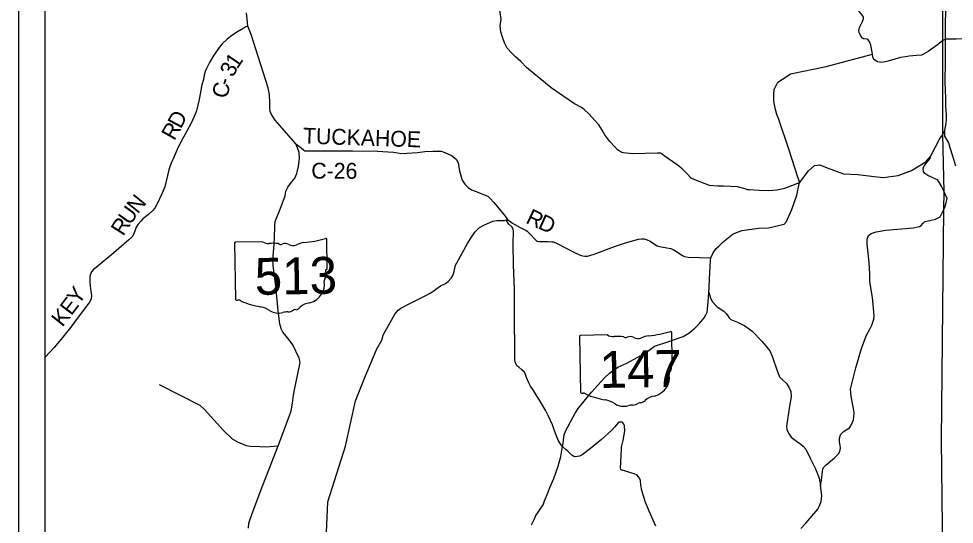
# Model space of a CAD drawing. Extents: x 0 to 2329303, y 0 to 694397.
# Drawn here: x 2 to 5.532, y 18.082 to 19.992 of the extents above; entities that cross this region are included whole.
import ezdxf

# ---------------------------------------------------------------- set-up
doc = ezdxf.new("R2010")
doc.units = 0
for name, color, linetype in [('GM_X_County_Road', 7, 'Continuous'), ('GM_X_County_Road_Text', 7, 'Continuous'), ('GM_X_State_Route', 7, 'Continuous'), ('GM_X_State_Shield', 7, 'Continuous'), ('GM_X_Township', 7, 'Continuous'), ('GM_X_Township_Road', 7, 'Continuous'), ('GM_X_Township_ROW', 7, 'Continuous'), ('SH_Data', 7, 'Continuous')]:
    doc.layers.add(name, color=color, linetype=linetype)

msp = doc.modelspace()

# ---------------------------------------------------------------- linework, layer by layer
at = {"layer": 'GM_X_County_Road'}
for points in [[(2.8652, 19.9647), (2.858, 19.9618), (2.8499, 19.9568), (2.8255, 19.9424), (2.8044, 19.9283), (2.787, 19.9145), (2.7664, 19.8965), (2.7605, 19.889), (2.7373, 19.855), (2.7203, 19.8264), (2.7089, 19.8039), (2.7042, 19.793), (2.7007, 19.7789), (2.6972, 19.7624), (2.6909, 19.7431), (2.6902, 19.7359), (2.6859, 19.715), (2.6813, 19.6877), (2.6712, 19.6443), (2.6626, 19.623), (2.65, 19.5948), (2.6227, 19.5444), (2.6018, 19.5065), (2.5864, 19.4719), (2.5754, 19.4465), (2.5707, 19.4333), (2.5672, 19.4216), (2.5613, 19.3995), (2.5513, 19.3577), (2.5406, 19.3303), (2.5229, 19.2925), (2.5146, 19.2788), (2.5071, 19.2695), (2.49, 19.2529), (2.4689, 19.2363), (2.4605, 19.2274), (2.451, 19.2157), (2.4439, 19.2044), (2.4396, 19.1935), (2.4329, 19.177), (2.4286, 19.1686), (2.4154, 19.1572), (2.3593, 19.1074), (2.2925, 19.0524), (2.2825, 19.0443), (2.2754, 19.0358), (2.271, 19.0273), (2.2687, 19.0177), (2.2681, 18.9968), (2.2707, 18.9712), (2.2732, 18.9543), (2.2748, 18.9467), (2.2738, 18.9331), (2.2674, 18.9218), (2.2555, 18.906), (2.225, 18.8645), (2.1973, 18.8266), (2.1854, 18.8128), (2.1663, 18.7894), (2.1334, 18.7495), (2.1, 18.7133)], [(3.0469, 19.5191), (3.0659, 19.504), (3.0764, 19.4953), (3.0804, 19.4933), (3.0988, 19.4926), (3.2602, 19.4935), (3.3543, 19.4914), (3.3952, 19.4897), (3.4156, 19.4882), (3.4304, 19.4859), (3.4461, 19.4836), (3.4653, 19.4838), (3.5053, 19.4869), (3.5329, 19.4903), (3.5653, 19.4917), (3.5862, 19.4923), (3.595, 19.4916), (3.6094, 19.4873), (3.6335, 19.4754), (3.6456, 19.4667), (3.6533, 19.4599), (3.6594, 19.4463), (3.6648, 19.4174), (3.6702, 19.3954), (3.6747, 19.3822), (3.6844, 19.3674), (3.6965, 19.3551), (3.7102, 19.3463), (3.7271, 19.3396), (3.7608, 19.3259), (3.7713, 19.3215), (3.7805, 19.3136), (3.7943, 19.2984), (3.8331, 19.2517), (3.846, 19.2338), (3.8525, 19.229), (3.8645, 19.2203), (3.8911, 19.2052), (3.9088, 19.1965), (3.9148, 19.1933), (3.92, 19.1902), (3.9305, 19.1786), (3.9495, 19.1579), (3.9568, 19.1523), (3.9668, 19.15), (3.9996, 19.1502), (4.0128, 19.1499), (4.0197, 19.1492), (4.0325, 19.1424), (4.0956, 19.11), (4.1198, 19.0993), (4.1294, 19.0958), (4.1378, 19.0951), (4.1478, 19.0955), (4.173, 19.1033), (4.2492, 19.132), (4.2912, 19.1452), (4.3403, 19.1592), (4.3515, 19.1605), (4.3612, 19.1601), (4.3728, 19.157), (4.3844, 19.1515), (4.3973, 19.1431), (4.4106, 19.1348), (4.4255, 19.1305), (4.4623, 19.1244), (4.4708, 19.1208), (4.4841, 19.1125), (4.4998, 19.101), (4.5066, 19.0974), (4.5134, 19.0934), (4.5279, 19.0919), (4.6135, 19.0889)]]:
    msp.add_lwpolyline(points, dxfattribs=at)
at = {"layer": 'GM_X_State_Route'}
for points in [[(5.4896, 19.5547), (5.4963, 19.5711), (5.5005, 19.5907), (5.503, 19.6107), (5.5027, 19.6294), (5.5009, 19.6616), (5.5008, 19.6926), (5.4982, 19.7527), (5.4993, 19.8307), (5.4998, 19.9151), (5.4988, 19.9776), (5.5001, 20.0174), (5.4999, 20.0298), (5.5007, 20.033)], [(2.8679, 18.0674), (2.8691, 18.0862), (2.871, 18.0943), (2.8812, 18.1226), (2.922, 18.2293), (2.9555, 18.317), (2.9798, 18.379), (2.9978, 18.4249), (3.0229, 18.4936), (3.0285, 18.5106), (3.0336, 18.5396), (3.0378, 18.5702), (3.0428, 18.5963), (3.0608, 18.6806), (3.0619, 18.6874), (3.0625, 18.695), (3.0594, 18.7094), (3.0352, 18.7595), (3.0249, 18.7746), (3.0048, 18.7986), (2.9974, 18.8077), (2.992, 18.8177), (2.9864, 18.8376), (2.9797, 18.8893), (2.9711, 18.9818), (2.9649, 19.0302), (2.9611, 19.0607), (2.9591, 19.0811), (2.9622, 19.1093), (2.9647, 19.1402), (2.9658, 19.1687), (2.9667, 19.2049), (2.9672, 19.2165), (2.9698, 19.2294), (2.985, 19.2666), (3.0056, 19.3232), (3.0092, 19.341), (3.0161, 19.3559), (3.0262, 19.3698), (3.0423, 19.3902), (3.0507, 19.408), (3.0566, 19.4342), (3.0608, 19.466), (3.0592, 19.4868), (3.0532, 19.5044), (3.0469, 19.5191), (2.9953, 19.5783), (2.9682, 19.609), (2.955, 19.6305), (2.9496, 19.6412), (2.9481, 19.654), (2.9482, 19.6729), (2.9467, 19.7061), (2.9414, 19.7309), (2.8953, 19.8771), (2.8776, 19.9321), (2.8652, 19.9647), (2.8627, 19.9922), (2.8606, 20.0144)], [(5.5387, 19.4355), (5.5273, 19.4728), (5.5172, 19.5043), (5.512, 19.5232), (5.4971, 19.5489), (5.4963, 19.5711)], [(3.9361, 18.0806), (3.9472, 18.1029), (3.953, 18.1159), (3.9592, 18.124), (3.9694, 18.139), (3.9798, 18.1557), (3.9855, 18.171), (3.9989, 18.203), (4.005, 18.2212), (4.0207, 18.2552), (4.037, 18.302), (4.0471, 18.3387), (4.0536, 18.3758), (4.0553, 18.3878), (4.0585, 18.4116), (4.0595, 18.42), (4.0648, 18.4338), (4.1004, 18.5015), (4.1128, 18.5194), (4.1628, 18.5813), (4.1867, 18.6075), (4.213, 18.6373), (4.2307, 18.6525), (4.2425, 18.6615), (4.2623, 18.676), (4.2964, 18.6911), (4.3352, 18.7119), (4.363, 18.7273), (4.3799, 18.7405), (4.3906, 18.7479), (4.4005, 18.7545), (4.4542, 18.7728), (4.4939, 18.7869), (4.5094, 18.792), (4.5308, 18.804), (4.5525, 18.8225), (4.5686, 18.8393), (4.5877, 18.8626), (4.5939, 18.8731), (4.5989, 18.8841), (4.6017, 18.907), (4.6046, 18.9392), (4.6058, 18.9586), (4.6067, 18.9737), (4.6088, 19.0111), (4.6107, 19.0549), (4.6114, 19.079), (4.6135, 19.0889), (4.614, 19.0915), (4.6217, 19.1077), (4.633, 19.124), (4.644, 19.1326), (4.6603, 19.1498), (4.6979, 19.1801), (4.7304, 19.1926), (4.7934, 19.2011), (4.8314, 19.2017), (4.8899, 19.2157), (4.898, 19.224), (4.9195, 19.2719), (4.9381, 19.325), (4.9465, 19.3689), (4.9496, 19.3733), (4.9804, 19.4167), (5.0042, 19.4374), (5.0246, 19.44), (5.0525, 19.4287), (5.1143, 19.4067), (5.1689, 19.4034), (5.2303, 19.3962), (5.2636, 19.3919), (5.3211, 19.3994), (5.3705, 19.4188), (5.4225, 19.4503), (5.4436, 19.4746), (5.4766, 19.5376), (5.4896, 19.5547)]]:
    msp.add_lwpolyline(points, dxfattribs=at)
at = {"layer": 'GM_X_State_Shield'}
for p, q in [((2.9206, 19.1493), (2.8187, 19.1476)), ((3.165, 19.0481), (3.1632, 19.1586)), ((2.8153, 19.1439), (2.8189, 18.9326)), ((3.165, 19.0481), (3.165, 19.0481)), ((4.2229, 18.7975), (4.121, 18.7958)), ((4.4674, 18.6963), (4.4655, 18.8069)), ((4.1177, 18.7921), (4.1212, 18.5809)), ((4.4673, 18.6964), (4.4674, 18.6963))]:
    msp.add_line(p, q, dxfattribs=at)
for centre, major_axis, start_param, end_param in [((2.8193, 19.1444), (0.00403, 0.00007), 1.712693, 3.28349), ((2.9444, 19.1742), (0.0391, 0.0007), 4.042523, 4.731795), ((3.0874, 19.0876), (0.0742, 0.0012), 1.699011, 2.107814), ((3.0345, 19.4394), (0.369, 0.0062), 4.814394, 5.042369), ((3.1593, 19.159), (0.00387, 0.00006), 6.141152, 7.989035), ((2.9598, 19.0313), (0.1404, 0.0024), 1.404758, 1.657858), ((2.9897, 19.1484), (0.0113, 0.0002), 3.836095, 5.185415), ((3.0067, 19.1242), (0.0235, 0.0004), 0.950623, 2.079405), ((3.0364, 19.1582), (0.0282, 0.0005), 4.081561, 5.145723), ((3.1643, 19.04), (0.006, 0.0001), 1.883978, 3.671073), ((3.1609, 19.0476), (0.00415, 0.00007), 5.05454, 6.418171), ((3.1797, 19.0021), (0.0262, 0.0004), 2.387724, 3.262537), ((3.1263, 19.0253), (0.036, 0.0006), 5.934695, 6.695948), ((3.0627, 18.986), (0.0923, 0.0015), 5.101752, 6.440018), ((2.8229, 18.9322), (0.00407, 0.00007), 3.00124, 4.508301), ((2.8231, 18.9538), (0.031, 0.0005), 4.665946, 4.897461), ((2.8301, 18.9206), (0.0112, 0.0002), 0.519207, 1.627899), ((2.9682, 19.1128), (0.2665, 0.0045), 4.195997, 4.488961), ((2.8933, 18.8389), (0.0834, 0.0014), 0.823519, 1.323587), ((3.0388, 18.9158), (0.0298, 0.0005), 4.937069, 5.64225), ((3.1035, 18.878), (0.0506, 0.0008), 1.647645, 2.488434), ((2.9821, 18.9221), (0.0529, 0.0009), 4.026481, 4.996735), ((3.0139, 18.8496), (0.0435, 0.0007), 1.495662, 1.94098), ((3.0168, 18.9069), (0.0282, 0.0005), 4.691044, 5.507374), ((3.0426, 18.8868), (0.00794, 0.00013), 1.147584, 2.315152), ((4.1216, 18.7927), (0.00403, 0.00007), 1.712693, 3.28349), ((4.2468, 18.8225), (0.0391, 0.0007), 4.042523, 4.731795), ((4.3898, 18.7358), (0.0742, 0.0012), 1.699011, 2.107814), ((4.3368, 19.0876), (0.369, 0.0062), 4.814394, 5.042369), ((4.4616, 18.8073), (0.00387, 0.00006), 6.141152, 7.989035), ((4.2622, 18.6795), (0.1404, 0.0024), 1.404758, 1.657858), ((4.2921, 18.7966), (0.0113, 0.0002), 3.836095, 5.185415), ((4.3091, 18.7725), (0.0235, 0.0004), 0.950623, 2.079405), ((4.3388, 18.8065), (0.0282, 0.0005), 4.081561, 5.145723), ((4.4666, 18.6882), (0.006, 0.0001), 1.883978, 3.671073), ((4.4632, 18.6958), (0.00415, 0.00007), 5.05454, 6.418171), ((4.482, 18.6503), (0.0262, 0.0004), 2.387724, 3.262537), ((4.4287, 18.6736), (0.036, 0.0006), 5.934695, 6.695948), ((4.3651, 18.6343), (0.0923, 0.0015), 5.101752, 6.440018), ((4.1252, 18.5805), (0.00407, 0.00007), 3.00124, 4.508301), ((4.1255, 18.6021), (0.031, 0.0005), 4.665946, 4.897461), ((4.1324, 18.5688), (0.0112, 0.0002), 0.519207, 1.627899), ((4.2705, 18.7611), (0.2665, 0.0045), 4.195997, 4.488961), ((4.1956, 18.4871), (0.0834, 0.0014), 0.823519, 1.323587), ((4.3411, 18.5641), (0.0298, 0.0005), 4.937069, 5.64225), ((4.4058, 18.5263), (0.0506, 0.0008), 1.647645, 2.488434), ((4.2845, 18.5703), (0.0529, 0.0009), 4.026481, 4.996735), ((4.3163, 18.4978), (0.0435, 0.0007), 1.495662, 1.94098), ((4.3192, 18.5551), (0.0282, 0.0005), 4.691044, 5.507374), ((4.345, 18.5351), (0.00794, 0.00013), 1.147584, 2.315152)]:
    msp.add_ellipse(centre, major_axis=major_axis, ratio=0.8, start_param=start_param, end_param=end_param, dxfattribs=at)
at = {"layer": 'GM_X_Township'}
msp.add_lwpolyline([(5.8223, 14.1123), (5.5, 14.1), (5.5092, 14.6075), (5.4849, 16.2502), (5.4862, 16.3702), (5.4966, 17.3083), (5.484, 18.4012), (5.4927, 19.2711), (5.4941, 19.3381), (5.4896, 19.5547), (5.4893, 19.9096), (5.4898, 20.0261), (5.5032, 20.182), (5.5028, 20.3048), (5.5027, 20.3409), (5.5308, 20.3409), (5.6417, 20.3416)], dxfattribs=at)
at = {"layer": 'GM_X_Township_Road'}
for points in [[(4.9496, 19.3733), (4.9273, 19.365), (4.891, 19.351), (4.864, 19.3449), (4.8309, 19.3422), (4.7961, 19.343), (4.7596, 19.3455), (4.7512, 19.3456), (4.7431, 19.3493), (4.7141, 19.3572), (4.6608, 19.3602), (4.6391, 19.3601), (4.6079, 19.3619), (4.5529, 19.3831), (4.5392, 19.3902), (4.5239, 19.4062), (4.5049, 19.4249), (4.4863, 19.44), (4.4376, 19.4746), (4.4312, 19.4793), (4.4231, 19.4837), (4.4119, 19.4844), (4.3171, 19.4813), (4.2834, 19.4851), (4.2774, 19.487), (4.2609, 19.4973), (4.2504, 19.5077), (4.2322, 19.5288), (4.2136, 19.5532), (4.2034, 19.5708), (4.1905, 19.5911), (4.1771, 19.6071), (4.1521, 19.6326), (4.1344, 19.6489), (4.1243, 19.6564), (4.0982, 19.6703), (4.01, 19.731), (3.9173, 19.8082), (3.8964, 19.8301), (3.8754, 19.8488), (3.8625, 19.8619), (3.8443, 19.881), (3.8346, 19.9014), (3.8268, 19.9222), (3.8198, 19.943), (3.8181, 19.9651), (3.8211, 19.9908), (3.8144, 20.041)], [(5.2134, 19.9026), (5.2133, 19.9029), (5.213, 19.9036), (5.21, 19.9091), (5.2071, 19.913), (5.2038, 19.9149), (5.1898, 19.9169), (5.1861, 19.9188), (5.1791, 19.9265), (5.173, 19.94), (5.1719, 19.9484), (5.1748, 19.9597), (5.1856, 19.9813), (5.1897, 19.993), (5.1899, 19.997), (5.1873, 20.0026), (5.174, 20.0186), (5.1706, 20.0237), (5.1688, 20.0296), (5.1702, 20.0365), (5.1748, 20.0519)], [(5.8316, 19.9029), (5.8187, 19.9068), (5.8056, 19.9139), (5.7948, 19.92), (5.7881, 19.9235), (5.7783, 19.9269), (5.7671, 19.9301), (5.7476, 19.9336), (5.7327, 19.9354), (5.7148, 19.9371), (5.6967, 19.9367), (5.6229, 19.9279), (5.5968, 19.9235), (5.5703, 19.9167), (5.5393, 19.9154), (5.5174, 19.9154), (5.4998, 19.9151), (5.4893, 19.9096)], [(5.4893, 19.9096), (5.4689, 19.8932), (5.4333, 19.8684), (5.4164, 19.8586), (5.4082, 19.8551), (5.3902, 19.8537), (5.3619, 19.8508), (5.3479, 19.8485), (5.3478, 19.8484)], [(4.9012, 19.7751), (4.9015, 19.7753), (4.9142, 19.7836), (5.0481, 19.8112), (5.0623, 19.815)], [(4.9496, 19.3733), (4.9425, 19.3896), (4.9073, 19.4991), (4.8703, 19.6121), (4.8625, 19.6307), (4.8562, 19.6538), (4.8512, 19.6821), (4.8508, 19.7061), (4.8526, 19.7254), (4.8657, 19.7523), (4.9012, 19.7751)], [(5.4941, 19.3381), (5.4842, 19.3601), (5.477, 19.3723), (5.4732, 19.3786), (5.469, 19.3833), (5.4597, 19.3874), (5.4321, 19.3993), (5.4218, 19.407), (5.4168, 19.4156), (5.4148, 19.4248), (5.4181, 19.4337), (5.4331, 19.4535), (5.4419, 19.4642), (5.4436, 19.4746)], [(5.4927, 19.2711), (5.4966, 19.2805), (5.5019, 19.2972), (5.5053, 19.3138), (5.4983, 19.3287), (5.4941, 19.3381)], [(5.0279, 18.2286), (5.0312, 18.2487), (5.0353, 18.2821), (5.0366, 18.2898), (5.0392, 18.2967), (5.0489, 18.3062), (5.08, 18.3337), (5.0951, 18.3482), (5.1004, 18.3568), (5.1032, 18.3701), (5.1017, 18.3797), (5.0992, 18.394), (5.0989, 18.4032), (5.1006, 18.4125), (5.1046, 18.4231), (5.1135, 18.4318), (5.1308, 18.4424), (5.1362, 18.4461), (5.142, 18.4536), (5.1516, 18.4771), (5.1548, 18.5017), (5.1537, 18.512), (5.1431, 18.5662), (5.1415, 18.5778), (5.141, 18.5922), (5.1451, 18.6128), (5.1603, 18.6738), (5.1819, 18.7459), (5.1907, 18.7706), (5.2014, 18.797), (5.2119, 18.8166), (5.2209, 18.8346), (5.2286, 18.8577), (5.2297, 18.8714), (5.2235, 18.9385), (5.216, 18.9832), (5.2142, 19.0012), (5.2137, 19.0284), (5.2107, 19.0708), (5.2059, 19.1184), (5.2036, 19.1399), (5.2037, 19.1596), (5.2081, 19.1726), (5.2186, 19.1813), (5.2372, 19.1868), (5.2742, 19.1928), (5.3771, 19.2018), (5.4013, 19.2074), (5.4072, 19.2108), (5.4141, 19.2187), (5.4211, 19.2257), (5.4401, 19.2304), (5.4619, 19.2355), (5.4788, 19.2441), (5.4927, 19.2711)], [(4.4062, 18.0751), (4.3801, 18.1315), (4.3651, 18.1687), (4.3585, 18.1891), (4.3523, 18.2103), (4.349, 18.2295), (4.3473, 18.2479), (4.3444, 18.2559), (4.3407, 18.2619), (4.3347, 18.2675), (4.3242, 18.2726), (4.2781, 18.2863), (4.2753, 18.2871), (4.2737, 18.2891), (4.2728, 18.2947), (4.2755, 18.3653), (4.2758, 18.3738), (4.2817, 18.3991), (4.2886, 18.4356), (4.2872, 18.4549), (4.2848, 18.4609), (4.2816, 18.4653), (4.2775, 18.4677), (4.2711, 18.4684), (4.2667, 18.4676), (4.2631, 18.4651), (4.2492, 18.449), (4.2393, 18.4377), (4.1999, 18.4021), (4.1585, 18.3681), (4.1271, 18.3442), (4.1175, 18.3393), (4.1091, 18.3376), (4.1011, 18.3368), (4.0955, 18.3379), (4.0887, 18.3427), (4.0733, 18.3586), (4.0669, 18.3634), (4.0536, 18.3758), (4.0447, 18.3869), (4.037, 18.4005), (4.0268, 18.4253), (4.0149, 18.4581), (4.0003, 18.4901), (3.9901, 18.5105), (3.9702, 18.5448), (3.9431, 18.588), (3.9329, 18.6043), (3.9252, 18.6195), (3.9171, 18.6363), (3.9138, 18.6475), (3.9093, 18.6563), (3.9, 18.6659), (3.8887, 18.6762), (3.8811, 18.6814), (3.8778, 18.6854), (3.8742, 18.6954), (3.8733, 18.7046), (3.8728, 18.7684), (3.8719, 18.8306), (3.8714, 18.9056), (3.8716, 18.9723), (3.8678, 19.0605), (3.8671, 19.142), (3.8684, 19.189), (3.8671, 19.1966), (3.8623, 19.2062), (3.851, 19.2166), (3.8429, 19.2273), (3.846, 19.2338)], [(4.6058, 18.9586), (4.6123, 18.9376), (4.6189, 18.9244), (4.6362, 18.9045), (4.6634, 18.8855), (4.6708, 18.8786), (4.6779, 18.87), (4.6821, 18.8625), (4.6887, 18.8559), (4.7135, 18.8463), (4.7419, 18.8316), (4.7685, 18.8132), (4.8075, 18.7724), (4.8359, 18.7369), (4.8453, 18.7167), (4.8515, 18.6985), (4.8573, 18.6807), (4.8679, 18.6521), (4.871, 18.643), (4.8727, 18.6391), (4.8798, 18.6317), (4.8991, 18.6139), (4.9076, 18.6001), (4.9158, 18.5832), (4.916, 18.5631), (4.91, 18.5289), (4.8989, 18.4531), (4.9005, 18.4408), (4.9065, 18.4265), (4.9171, 18.4109), (4.9368, 18.3959), (4.9527, 18.3848), (4.9622, 18.3775), (4.9717, 18.3662), (4.9885, 18.3315), (5.009, 18.2913), (5.0229, 18.2565), (5.0279, 18.2286)], [(2.5306, 18.6097), (2.6837, 18.5316), (2.702, 18.5156), (2.7731, 18.4365), (2.8065, 18.4054), (2.8256, 18.3934), (2.859, 18.3792), (2.8736, 18.3769), (2.9119, 18.3762), (2.9338, 18.3742), (2.9798, 18.379)], [(4.9533, 18.0658), (4.9714, 18.0869), (5.0172, 18.1397), (5.0229, 18.1487), (5.0299, 18.1677), (5.0327, 18.1911), (5.0279, 18.2286)]]:
    msp.add_lwpolyline(points, dxfattribs=at)
at = {"layer": 'GM_X_Township_ROW'}
for points in [[(5.3478, 19.8484), (5.3293, 19.8453), (5.3075, 19.8394), (5.2782, 19.8304), (5.2579, 19.8273), (5.2422, 19.8296), (5.2292, 19.8384), (5.2252, 19.8483), (5.2235, 19.8581), (5.2223, 19.8654), (5.2174, 19.8921), (5.2134, 19.9026)], [(5.0623, 19.815), (5.0627, 19.8151), (5.2235, 19.8581)], [(3.156, 17.9067), (3.1669, 18.1666), (3.2334, 18.3777), (3.271, 18.5489), (3.3099, 18.6435), (3.3397, 18.7146), (3.3524, 18.7449), (3.3706, 18.7779), (3.3764, 18.7964), (3.38, 18.8041), (3.3899, 18.8222), (3.4207, 18.8762), (3.433, 18.8916), (3.4433, 18.8989), (3.4689, 18.9127), (3.5319, 18.9441), (3.553, 18.9559), (3.569, 18.9652), (3.5781, 18.9733), (3.5921, 18.9826), (3.6112, 18.9916), (3.6212, 18.9993), (3.6327, 19.0114), (3.6386, 19.0215), (3.6437, 19.0376), (3.6495, 19.0609), (3.6543, 19.0702), (3.6946, 19.1427), (3.7072, 19.1633), (3.7223, 19.1859), (3.7401, 19.2037), (3.7581, 19.2139), (3.7896, 19.2273), (3.8056, 19.2299), (3.818, 19.2299), (3.8344, 19.2301), (3.846, 19.2338)]]:
    msp.add_lwpolyline(points, dxfattribs=at)
at = {"layer": 'SH_Data'}
for points in [[(2, 21), (9, 21), (9, 14), (2, 14)], [(2.1, 20.9), (8.9, 20.9), (8.9, 14.1), (2.1, 14.1)]]:
    msp.add_lwpolyline(points, close=True, dxfattribs=at)

# ---------------------------------------------------------------- texts
at = {"layer": 'GM_X_County_Road_Text'}
for s, rotation, p in [('1', 55.6662, (2.8248, 19.7998)), ('3', 61.9826, (2.8089, 19.7684)), ('C', 77.8924, (2.7875, 19.6885)), ('-', 72.5426, (2.7967, 19.7354)), ('D', 62.048, (2.6119, 19.5736)), ('R', 60.6516, (2.5877, 19.5289)), ('TUCKAHOE', 358.1241, (3.0726, 19.5206)), ('C-26', 359.6571, (3.1046, 19.3883)), ('N', 51.1217, (2.4495, 19.2521)), ('U', 54.0947, (2.4197, 19.2095)), ('R', 334.7843, (3.911, 19.2221)), ('D', 335.969, (3.9571, 19.2013)), ('R', 57.4932, (2.3945, 19.1683)), ('Y', 54.6405, (2.2264, 18.9082)), ('E', 52.6032, (2.1982, 18.8676)), ('K', 51.3297, (2.165, 18.8246))]:
    msp.add_text(s, height=0.06, rotation=rotation, dxfattribs=at).set_placement(p)
at = {"layer": 'GM_X_State_Shield'}
for s, p in [('513', (2.8924, 18.9487)), ('147', (4.1943, 18.597))]:
    msp.add_text(s, height=0.13922, rotation=0.961, dxfattribs=at).set_placement(p)

doc.saveas('drawing.dxf')
